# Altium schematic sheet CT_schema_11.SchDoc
size 254 x 194 mm
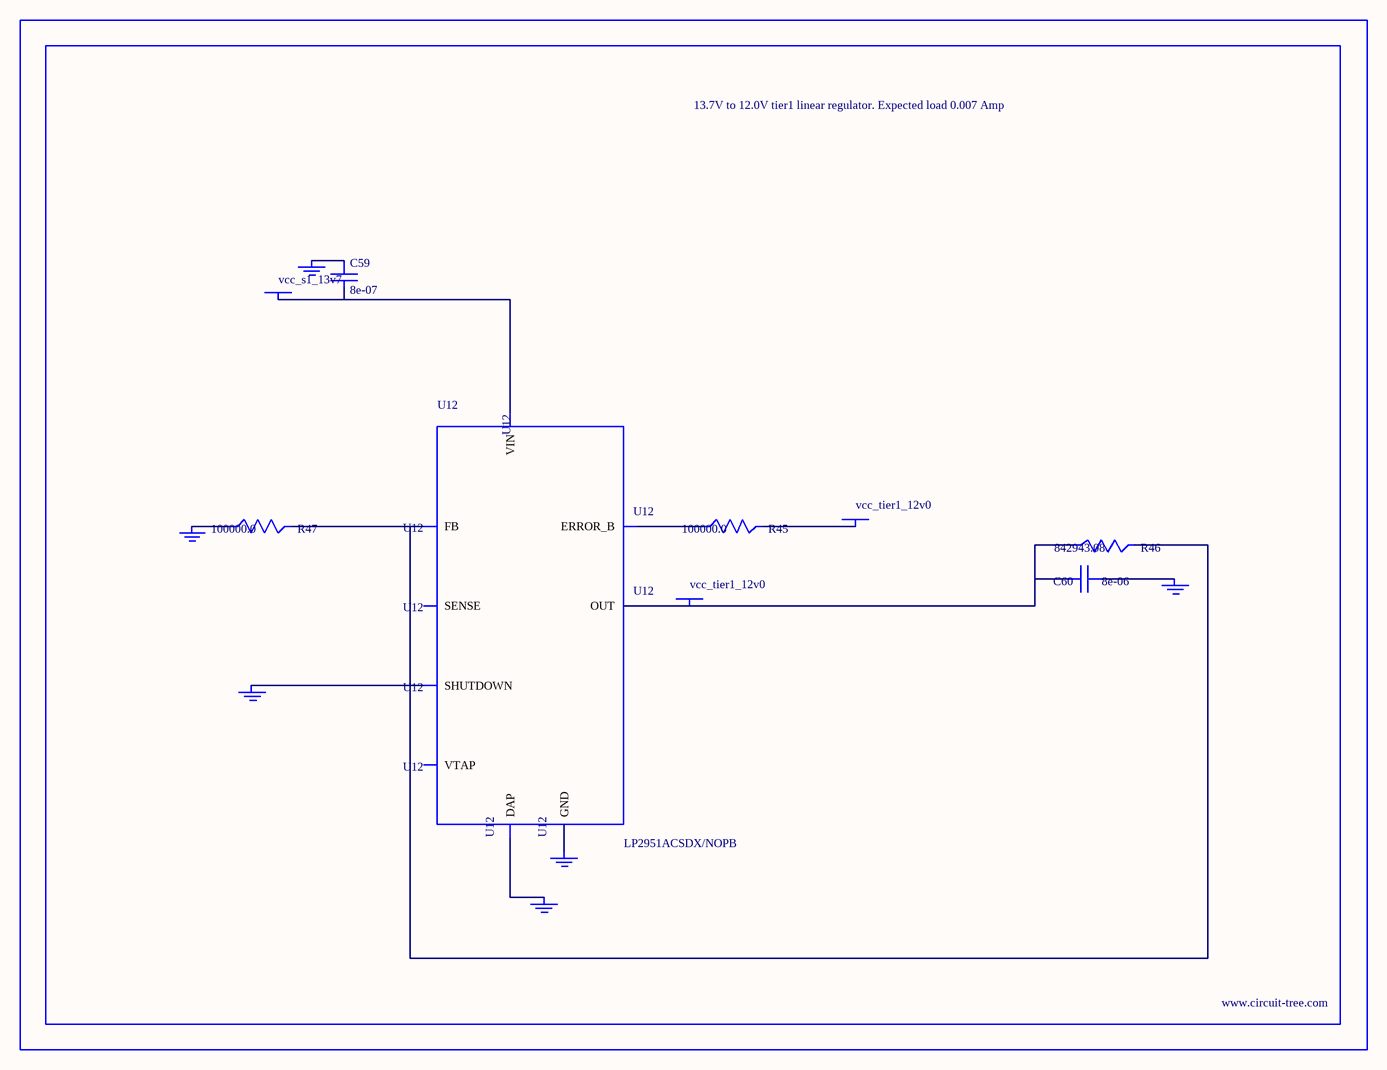
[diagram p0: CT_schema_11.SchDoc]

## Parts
BORDER10  (no value)
C59  8e-07  [R0603]
C60  8e-06  [R0603]
GND_INSTANCE_10_0  (no value)
GND_INSTANCE_10_1  (no value)
GND_INSTANCE_10_2  (no value)
GND_INSTANCE_10_3  (no value)
GND_INSTANCE_10_4  (no value)
GND_INSTANCE_10_5  (no value)
POWER_INSTANCE_10_0  vcc_tier1_12v0
POWER_INSTANCE_10_1  vcc_s1_13v7
POWER_INSTANCE_10_2  vcc_tier1_12v0
R45  100000.0  [R0603]
R46  842943.08  [R0603]
R47  100000.0  [R0603]
U12  LP2951ACSDX/NOPB  [WSON-8]

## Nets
NetC59_1: C59.1 GND_INSTANCE_10_3.0(GND)
NetC59_2: C59.2 POWER_INSTANCE_10_1.0(PWR) U12.8(VIN)
NetC60_1: C60.1 GND_INSTANCE_10_0.0(GND)
NetC60_2: C60.2 POWER_INSTANCE_10_2.0(PWR) R46.1 U12.1(OUT)
NetGND_INSTANCE_10_1_0: GND_INSTANCE_10_1.0(GND) U12.3(SHUTDOWN)
NetGND_INSTANCE_10_2_0: GND_INSTANCE_10_2.0(GND) R47.1
NetGND_INSTANCE_10_4_0: GND_INSTANCE_10_4.0(GND) U12.PAD(DAP)
NetGND_INSTANCE_10_5_0: GND_INSTANCE_10_5.0(GND) U12.4(GND)
NetPOWER_INSTANCE_10_0_0: POWER_INSTANCE_10_0.0(PWR) R45.2
NetR45_1: R45.1 U12.5(ERROR_B)
NetR46_2: R46.2 R47.2 U12.7(FB)

Not connected (* = marked no-connect by the designer): U12 2(SENSE) 6(VTAP)

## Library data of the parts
BORDER10 = BORDER_PAGE10
C59 = C59
C60 = C60
GND_INSTANCE_10_0-GND_INSTANCE_10_5 = GND
POWER_INSTANCE_10_0-POWER_INSTANCE_10_2 = PWR
R45 R47 = RC0603JR-07100KL
R46 = R46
